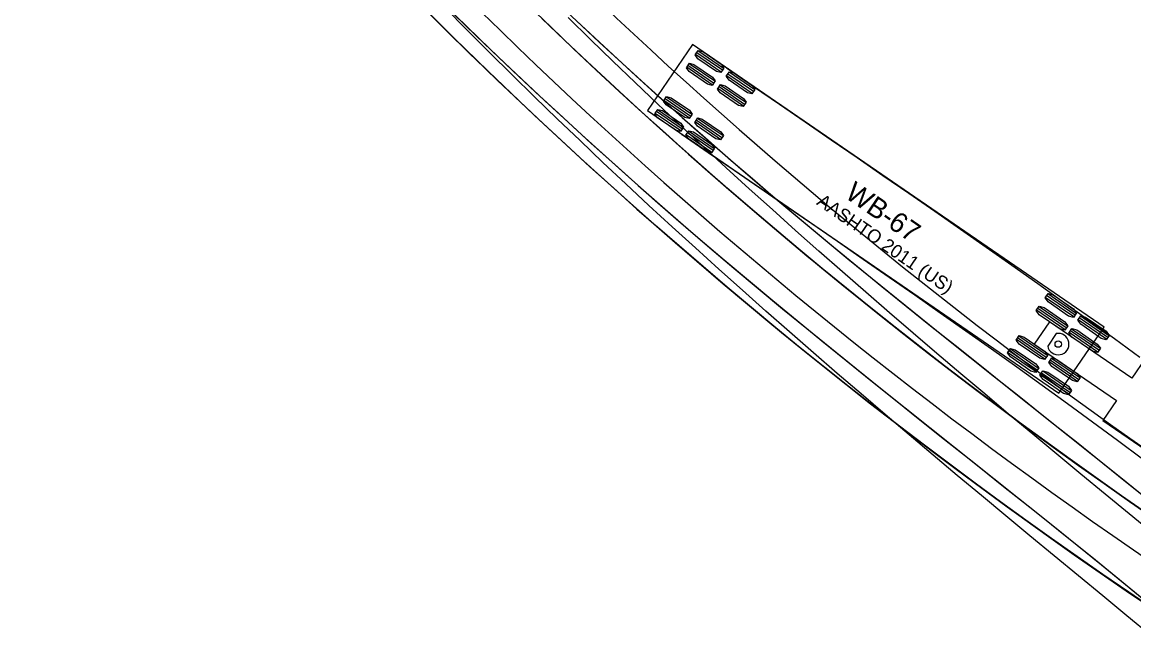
# Model space of a CAD drawing. Extents: x 916040 to 917457, y 328936 to 330267.
# Drawn here: x 916385 to 916503, y 330006.6 to 330071.7 of the extents above; entities that cross this region are included whole.
import ezdxf

# ---------------------------------------------------------------- set-up
doc = ezdxf.new("R2010")
doc.units = 0
for name, color, linetype in [('NB_ThruontoManchester_WB67', 7, 'Continuous'), ('SB_LeftontoRoute25_WB67', 7, 'Continuous'), ('SB_RightontoRoute25_WB67_v2', 7, 'Continuous'), ('SB_ThruontonSacoRd_WB67', 7, 'Continuous'), ('WB_RightontoManchester_WB67', 7, 'Continuous')]:
    doc.layers.add(name, color=color, linetype=linetype)

msp = doc.modelspace()

# ---------------------------------------------------------------- linework, layer by layer
at = {"layer": 'NB_ThruontoManchester_WB67'}
for p, q in [((916456.18, 330069.35), (916451.38, 330062.34)), ((916499.89, 330039.37), (916456.18, 330069.35)), ((916459.22, 330066.43), (916456.5, 330068.3)), ((916459.35, 330066.62), (916456.63, 330068.49)), ((916459.48, 330066.81), (916456.75, 330068.68)), ((916458.41, 330065.26), (916455.69, 330067.13)), ((916458.54, 330065.45), (916455.82, 330067.31)), ((916458.28, 330065.07), (916455.56, 330066.94)), ((916462.52, 330064.17), (916459.79, 330066.03)), ((916462.65, 330064.36), (916459.92, 330066.22)), ((916462.78, 330064.55), (916460.05, 330066.41)), ((916461.58, 330062.81), (916458.86, 330064.67)), ((916461.71, 330063), (916458.99, 330064.86)), ((916461.84, 330063.19), (916459.12, 330065.05)), ((916455.99, 330061.73), (916453.27, 330063.59)), ((916456.12, 330061.92), (916453.4, 330063.78)), ((916451.38, 330062.34), (916495.08, 330032.36)), ((916455.19, 330060.55), (916452.47, 330062.42)), ((916455.86, 330061.54), (916453.14, 330063.4)), ((916454.93, 330060.18), (916452.21, 330062.04)), ((916455.06, 330060.37), (916452.34, 330062.23)), ((916459.16, 330059.28), (916456.44, 330061.14)), ((916459.29, 330059.46), (916456.57, 330061.33)), ((916459.42, 330059.65), (916456.7, 330061.52)), ((916458.36, 330058.1), (916455.63, 330059.97)), ((916458.49, 330058.29), (916455.76, 330060.16)), ((916458.23, 330057.91), (916455.51, 330059.78)), ((916496.67, 330040.44), (916493.64, 330042.52)), ((916496.8, 330040.63), (916493.77, 330042.71)), ((916496.93, 330040.82), (916493.9, 330042.9)), ((916495.73, 330039.08), (916492.71, 330041.16)), ((916495.86, 330039.27), (916492.84, 330041.35)), ((916495.99, 330039.46), (916492.97, 330041.53)), ((916494.09, 330039.93), (916492.47, 330037.57)), ((916502.83, 330033.94), (916494.09, 330039.93)), ((916500.13, 330038.07), (916497.11, 330040.14)), ((916500.26, 330038.26), (916497.24, 330040.33)), ((916500.39, 330038.45), (916497.37, 330040.52)), ((916494.8, 330038.68), (916493.89, 330037.35)), ((916495.08, 330032.36), (916499.89, 330039.37)), ((916499.2, 330036.71), (916496.17, 330038.78)), ((916499.33, 330036.9), (916496.3, 330038.97)), ((916499.46, 330037.09), (916496.43, 330039.16)), ((916499.89, 330039.37), (916499.89, 330039.37)), ((916493.59, 330035.96), (916490.57, 330038.04)), ((916493.72, 330036.15), (916490.7, 330038.23)), ((916493.85, 330036.34), (916490.83, 330038.41)), ((916492.47, 330037.57), (916501.21, 330031.57)), ((916492.66, 330034.6), (916489.64, 330036.68)), ((916492.79, 330034.79), (916489.77, 330036.86)), ((916492.92, 330034.98), (916489.9, 330037.05)), ((916497.06, 330033.59), (916494.03, 330035.66)), ((916497.19, 330033.78), (916494.16, 330035.85)), ((916497.32, 330033.97), (916494.29, 330036.04)), ((916504.29, 330036.05), (916502.83, 330033.94)), ((916496.13, 330032.23), (916493.1, 330034.3)), ((916496.25, 330032.42), (916493.23, 330034.49)), ((916496.38, 330032.6), (916493.36, 330034.68)), ((916501.21, 330031.57), (916499.76, 330029.45)), ((916499.76, 330029.45), (916512.13, 330020.97))]:
    msp.add_line(p, q, dxfattribs=at)
for points in [[(916459.51, 330066.86), (916459.18, 330066.38), (916458.71, 330066.5), (916456.75, 330067.85), (916456.46, 330068.25), (916456.79, 330068.72), (916457.27, 330068.6), (916459.22, 330067.26)], [(916458.58, 330065.5), (916458.25, 330065.02), (916457.77, 330065.14), (916455.81, 330066.49), (916455.53, 330066.89), (916455.85, 330067.36), (916456.33, 330067.24), (916458.29, 330065.9)], [(916462.81, 330064.59), (916462.48, 330064.12), (916462.01, 330064.24), (916460.05, 330065.58), (916459.76, 330065.99), (916460.09, 330066.46), (916460.56, 330066.34), (916462.52, 330065)], [(916461.87, 330063.23), (916461.55, 330062.76), (916461.07, 330062.88), (916459.11, 330064.22), (916458.83, 330064.63), (916459.15, 330065.1), (916459.63, 330064.98), (916461.59, 330063.64)], [(916456.15, 330061.96), (916455.83, 330061.49), (916455.35, 330061.61), (916453.39, 330062.95), (916453.11, 330063.36), (916453.43, 330063.83), (916453.91, 330063.71), (916455.87, 330062.37)], [(916455.22, 330060.6), (916454.9, 330060.13), (916454.42, 330060.25), (916452.46, 330061.59), (916452.17, 330062), (916452.5, 330062.47), (916452.98, 330062.35), (916454.94, 330061.01)], [(916459.45, 330059.7), (916459.13, 330059.23), (916458.65, 330059.35), (916456.69, 330060.69), (916456.41, 330061.09), (916456.73, 330061.57), (916457.21, 330061.45), (916459.17, 330060.1)], [(916458.52, 330058.34), (916458.19, 330057.87), (916457.72, 330057.99), (916455.76, 330059.33), (916455.47, 330059.73), (916455.8, 330060.21), (916456.28, 330060.09), (916458.23, 330058.74)], [(916496.96, 330040.87), (916496.64, 330040.4), (916496.11, 330040.54), (916493.94, 330042.04), (916493.61, 330042.47), (916493.94, 330042.94), (916494.46, 330042.79), (916496.63, 330041.3)], [(916496.03, 330039.51), (916495.7, 330039.04), (916495.18, 330039.18), (916493, 330040.68), (916492.68, 330041.11), (916493, 330041.58), (916493.52, 330041.43), (916495.7, 330039.94)], [(916500.42, 330038.49), (916500.1, 330038.02), (916499.58, 330038.17), (916497.4, 330039.66), (916497.08, 330040.09), (916497.4, 330040.57), (916497.92, 330040.42), (916500.1, 330038.93)], [(916499.49, 330037.13), (916499.17, 330036.66), (916498.65, 330036.81), (916496.47, 330038.3), (916496.14, 330038.73), (916496.47, 330039.21), (916496.99, 330039.06), (916499.16, 330037.56)], [(916493.89, 330036.39), (916493.56, 330035.92), (916493.04, 330036.06), (916490.86, 330037.56), (916490.54, 330037.99), (916490.86, 330038.46), (916491.38, 330038.31), (916493.56, 330036.82)], [(916492.95, 330035.03), (916492.63, 330034.56), (916492.11, 330034.7), (916489.93, 330036.2), (916489.61, 330036.63), (916489.93, 330037.1), (916490.45, 330036.95), (916492.63, 330035.46)], [(916497.35, 330034.01), (916497.03, 330033.54), (916496.51, 330033.69), (916494.33, 330035.18), (916494, 330035.61), (916494.33, 330036.09), (916494.85, 330035.94), (916497.02, 330034.44)], [(916496.42, 330032.65), (916496.09, 330032.18), (916495.57, 330032.33), (916493.4, 330033.82), (916493.07, 330034.25), (916493.39, 330034.73), (916493.91, 330034.58), (916496.09, 330033.08)]]:
    msp.add_lwpolyline(points, close=True, dxfattribs=at)
for points in [[(916459.89, 330066.8), (916462.65, 330064.91), (916465.4, 330063.03), (916468.15, 330061.14), (916470.9, 330059.25), (916473.65, 330057.36), (916476.4, 330055.46), (916479.14, 330053.57), (916481.89, 330051.66), (916484.63, 330049.75), (916487.37, 330047.84), (916490.1, 330045.92), (916492.83, 330043.99), (916495.55, 330042.05), (916498.27, 330040.1), (916500.98, 330038.14), (916503.68, 330036.17)], [(916455.09, 330059.79), (916457.84, 330057.9), (916460.59, 330056.02), (916463.34, 330054.13), (916466.08, 330052.24), (916468.83, 330050.36), (916471.57, 330048.47), (916474.31, 330046.58), (916477.04, 330044.68), (916479.77, 330042.78), (916482.49, 330040.88), (916485.2, 330038.97), (916487.91, 330037.05), (916490.61, 330035.13), (916493.3, 330033.2), (916495.99, 330031.26), (916498.66, 330029.31), (916501.32, 330027.35), (916503.97, 330025.38)]]:
    msp.add_lwpolyline(points, dxfattribs=at)
for centre, radius in [((916459.89, 330066.8), 0.0417), ((916455.09, 330059.79), 0.0417), ((916495.01, 330037.56), 0.34)]:
    msp.add_circle(centre, radius, dxfattribs=at)
msp.add_arc((916495.01, 330037.56), 1.14, 190.5571, 100.5571, dxfattribs=at)
at = {"layer": 'SB_LeftontoRoute25_WB67'}
for points in [[(916438.77, 330073.49), (916441.15, 330071.19), (916443.55, 330068.9), (916445.96, 330066.64), (916448.39, 330064.38), (916450.83, 330062.15), (916453.29, 330059.93), (916455.76, 330057.72), (916458.25, 330055.53), (916460.75, 330053.36), (916463.26, 330051.2), (916465.79, 330049.06), (916468.33, 330046.94), (916470.89, 330044.83), (916473.46, 330042.74), (916476.04, 330040.67), (916478.63, 330038.61), (916481.24, 330036.57), (916483.87, 330034.55), (916486.5, 330032.54), (916489.15, 330030.55), (916491.81, 330028.58), (916494.48, 330026.63), (916497.17, 330024.69), (916499.87, 330022.77), (916502.58, 330020.87), (916505.3, 330018.98)], [(916428.24, 330072.63), (916430.63, 330070.26), (916433.03, 330067.91), (916435.45, 330065.58), (916437.89, 330063.26), (916440.34, 330060.95), (916442.8, 330058.66), (916445.28, 330056.39), (916447.77, 330054.13), (916450.28, 330051.89), (916452.81, 330049.67), (916455.35, 330047.46), (916457.9, 330045.27), (916460.46, 330043.1), (916463.04, 330040.94), (916465.64, 330038.8), (916468.25, 330036.67), (916470.87, 330034.57), (916473.5, 330032.48), (916476.15, 330030.4), (916478.81, 330028.35), (916481.49, 330026.31), (916484.18, 330024.29), (916486.88, 330022.28), (916489.59, 330020.3), (916492.32, 330018.33), (916495.06, 330016.38), (916497.81, 330014.44), (916500.58, 330012.53), (916503.36, 330010.63)], [(916430.79, 330072.62), (916433.2, 330070.29), (916435.62, 330067.98), (916438.05, 330065.67), (916440.5, 330063.39), (916442.96, 330061.11), (916445.43, 330058.86), (916447.92, 330056.61), (916450.42, 330054.39), (916452.94, 330052.17), (916455.47, 330049.98), (916458.02, 330047.79), (916460.58, 330045.62), (916463.15, 330043.47), (916465.73, 330041.32), (916468.33, 330039.2), (916470.93, 330037.08), (916473.54, 330034.97), (916476.15, 330032.88), (916478.76, 330030.78), (916481.38, 330028.7), (916483.99, 330026.62), (916486.6, 330024.54), (916489.21, 330022.46), (916491.82, 330020.39), (916494.42, 330018.31), (916497.01, 330016.22), (916499.59, 330014.13), (916502.16, 330012.04), (916504.72, 330009.94)], [(916443.87, 330071.86), (916446.28, 330069.61), (916448.71, 330067.37), (916451.14, 330065.15), (916453.59, 330062.94), (916456.05, 330060.75), (916458.53, 330058.57), (916461.02, 330056.41), (916463.53, 330054.26), (916466.05, 330052.12), (916468.59, 330050), (916471.14, 330047.88), (916473.71, 330045.78), (916476.28, 330043.68), (916478.87, 330041.59), (916481.46, 330039.51), (916484.06, 330037.43), (916486.67, 330035.35), (916489.28, 330033.27), (916491.9, 330031.19), (916494.51, 330029.11), (916497.12, 330027.03), (916499.73, 330024.94), (916502.34, 330022.84), (916504.94, 330020.74)]]:
    msp.add_lwpolyline(points, dxfattribs=at)
msp.add_arc((916795.02, 330440.53), 515.5, 217.3089, 236.0807, dxfattribs=at)
at = {"layer": 'SB_RightontoRoute25_WB67_v2'}
for points in [[(916427.29, 330073.58), (916429.67, 330071.21), (916432.07, 330068.85), (916434.48, 330066.51), (916436.91, 330064.18), (916439.35, 330061.87), (916441.81, 330059.58), (916444.29, 330057.3), (916446.78, 330055.03), (916449.28, 330052.79), (916451.8, 330050.56), (916454.33, 330048.34), (916456.87, 330046.15), (916459.44, 330043.96), (916462.01, 330041.8), (916464.6, 330039.65), (916467.2, 330037.52), (916469.82, 330035.41), (916472.45, 330033.31), (916475.09, 330031.23), (916477.75, 330029.17), (916480.42, 330027.12), (916483.1, 330025.09), (916485.8, 330023.08), (916488.51, 330021.09), (916491.23, 330019.11), (916493.96, 330017.15), (916496.71, 330015.21), (916499.47, 330013.29), (916502.24, 330011.39), (916505.03, 330009.5)], [(916429.83, 330073.56), (916432.23, 330071.22), (916434.65, 330068.9), (916437.07, 330066.59), (916439.51, 330064.3), (916441.97, 330062.02), (916444.44, 330059.76), (916446.92, 330057.51), (916449.42, 330055.27), (916451.93, 330053.06), (916454.45, 330050.85), (916456.99, 330048.66), (916459.55, 330046.49), (916462.12, 330044.33), (916464.7, 330042.18), (916467.29, 330040.05), (916469.89, 330037.92), (916472.49, 330035.81), (916475.1, 330033.71), (916477.72, 330031.62), (916480.33, 330029.53), (916482.95, 330027.45), (916485.56, 330025.37), (916488.17, 330023.3), (916490.78, 330021.22), (916493.38, 330019.14), (916495.97, 330017.06), (916498.56, 330014.97), (916501.13, 330012.88), (916503.7, 330010.78)], [(916440.19, 330072.11), (916442.59, 330069.82), (916445, 330067.54), (916447.42, 330065.28), (916449.86, 330063.04), (916452.31, 330060.81), (916454.77, 330058.6), (916457.25, 330056.41), (916459.75, 330054.23), (916462.26, 330052.06), (916464.78, 330049.92), (916467.31, 330047.79), (916469.86, 330045.67), (916472.43, 330043.58), (916475, 330041.5), (916477.59, 330039.43), (916480.2, 330037.39), (916482.82, 330035.36), (916485.45, 330033.34), (916488.09, 330031.35), (916490.74, 330029.37), (916493.41, 330027.41), (916496.09, 330025.46), (916498.79, 330023.54), (916501.49, 330021.63), (916504.21, 330019.73)], [(916442.91, 330072.77), (916445.32, 330070.51), (916447.74, 330068.27), (916450.17, 330066.04), (916452.61, 330063.82), (916455.07, 330061.62), (916457.54, 330059.44), (916460.02, 330057.27), (916462.53, 330055.12), (916465.04, 330052.97), (916467.57, 330050.84), (916470.12, 330048.73), (916472.68, 330046.62), (916475.25, 330044.52), (916477.83, 330042.43), (916480.42, 330040.34), (916483.02, 330038.26), (916485.63, 330036.18), (916488.24, 330034.1), (916490.85, 330032.02), (916493.46, 330029.95), (916496.08, 330027.86), (916498.69, 330025.77), (916501.3, 330023.68), (916503.9, 330021.58)]]:
    msp.add_lwpolyline(points, dxfattribs=at)
msp.add_arc((916795.02, 330440.53), 515.5, 217.3089, 236.0807, dxfattribs=at)
at = {"layer": 'SB_ThruontonSacoRd_WB67'}
for points in [[(916505.24, 330009.37), (916502.49, 330011.22), (916499.75, 330013.1), (916497.02, 330015), (916494.29, 330016.92), (916491.58, 330018.86), (916488.87, 330020.82), (916486.18, 330022.8), (916483.49, 330024.8), (916480.82, 330026.82), (916478.15, 330028.85), (916475.5, 330030.91), (916472.86, 330032.98), (916470.23, 330035.07), (916467.62, 330037.18), (916465.02, 330039.3), (916462.43, 330041.45), (916459.86, 330043.61), (916457.3, 330045.78), (916454.75, 330047.98), (916452.22, 330050.19), (916449.7, 330052.41), (916447.19, 330054.66), (916444.7, 330056.92), (916442.23, 330059.19), (916439.77, 330061.48), (916437.32, 330063.79), (916434.89, 330066.11), (916432.47, 330068.45), (916430.07, 330070.81), (916427.69, 330073.18)], [(916504.88, 330006.61), (916502.31, 330008.72), (916499.73, 330010.84), (916497.15, 330012.96), (916494.57, 330015.09), (916492, 330017.21), (916489.43, 330019.35), (916486.86, 330021.48), (916484.29, 330023.63), (916481.73, 330025.78), (916479.17, 330027.93), (916476.62, 330030.1), (916474.08, 330032.27), (916471.54, 330034.45), (916469.01, 330036.64), (916466.49, 330038.85), (916463.97, 330041.06), (916461.47, 330043.28), (916458.98, 330045.51), (916456.49, 330047.76), (916454.02, 330050.01), (916451.55, 330052.28), (916449.1, 330054.56), (916446.66, 330056.85), (916444.23, 330059.16), (916441.81, 330061.47), (916439.4, 330063.8), (916437.01, 330066.15), (916434.63, 330068.5), (916432.26, 330070.87), (916429.91, 330073.25)], [(916504.48, 330019.55), (916501.73, 330021.46), (916499, 330023.39), (916496.29, 330025.33), (916493.59, 330027.28), (916490.9, 330029.25), (916488.23, 330031.24), (916485.58, 330033.24), (916482.94, 330035.26), (916480.31, 330037.3), (916477.7, 330039.35), (916475.11, 330041.41), (916472.53, 330043.5), (916469.96, 330045.6), (916467.41, 330047.71), (916464.87, 330049.84), (916462.34, 330051.99), (916459.83, 330054.16), (916457.33, 330056.33), (916454.85, 330058.53), (916452.39, 330060.74), (916449.93, 330062.97), (916447.49, 330065.21), (916445.07, 330067.47), (916442.66, 330069.74), (916440.27, 330072.03)], [(916505.13, 330017.41), (916502.55, 330019.53), (916499.98, 330021.64), (916497.42, 330023.76), (916494.85, 330025.89), (916492.3, 330028.01), (916489.74, 330030.14), (916487.2, 330032.28), (916484.66, 330034.42), (916482.13, 330036.57), (916479.61, 330038.73), (916477.09, 330040.89), (916474.59, 330043.06), (916472.09, 330045.24), (916469.6, 330047.43), (916467.12, 330049.63), (916464.66, 330051.83), (916462.2, 330054.05), (916459.76, 330056.28), (916457.32, 330058.52), (916454.9, 330060.77), (916452.49, 330063.04), (916450.09, 330065.31), (916447.71, 330067.6), (916445.33, 330069.9), (916442.97, 330072.21)]]:
    msp.add_lwpolyline(points, dxfattribs=at)
msp.add_arc((916795.02, 330440.53), 515.5, 217.3089, 236.0807, dxfattribs=at)
at = {"layer": 'WB_RightontoManchester_WB67'}
msp.add_arc((916795.02, 330440.53), 506, 217.3089, 235.5571, dxfattribs=at)

# ---------------------------------------------------------------- texts
at = {"layer": 'NB_ThruontoManchester_WB67'}
for s, height, p in [('WB-67', 2.125, (916472.25, 330053.17)), ('AASHTO 2011 (US)', 1.4167, (916469.26, 330052.43))]:
    msp.add_text(s, height=height, rotation=325.5571, dxfattribs=at).set_placement(p)

doc.saveas('drawing.dxf')
